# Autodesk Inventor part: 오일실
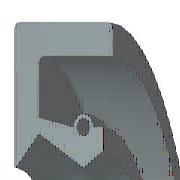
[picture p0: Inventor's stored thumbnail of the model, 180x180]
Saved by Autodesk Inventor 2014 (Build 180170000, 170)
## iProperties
Created: 2009-02
Part Number: 오일실
Material: 고무
Description: 오일-실
Document SubType Name: Modeling
Standard: KS B 2804
Designer: SeoGD™
Standards Organization: KS
Language: ko-KR
Size Designation: D - 10 20 7
Categories: <MemberInstance><Categories><Category DisplayName="샤프트 부품" InternalName="7f7aeb1f-a693-4053-b835-cee3144e0d98" Mnemonic="SHFT"><Category DisplayName="실링" Intern
Density: 0.93 g/cm^3
Mass: 1.11329 g
Surface Area: 16.3871 cm^2
Volume: 1.19708 cm^3
Appearance: 고무 - 검은색 - 버전 1.1
IsCustomPart: 0
Author: SeoGD™
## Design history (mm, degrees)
revolve "본체" stored, may be unused: angle "d17" = 90 deg
revolve "스프링1" stored, may be unused: angle "d18" = 90 deg
body "Solid1"
sketch "스케치1"
  geometry: L1 (0, 10)-(7, 10); L2 (7, 8.25)-(1.75, 8.25); L3 (1.75, 6.75)-(4.9, 5); L4 (4.9, 5)-(0, 5); L5 (0, 0)-(9.586, 0) reference; L6 (4.9, 5)-(6.3, 5.875); L7 (0, 18)-(0, -3) reference; L8 (-1.941, 0)-(11.507, 0) reference; L9 (4.2, 7.1)-(1.75, 7.59); L10 (1.75, 7.59)-(1.75, 8.25); L11 (0, 10)-(0, 5.088); L12 (4.9, 5)-(0, 5); L13 (1.75, 6.75)-(0.152, 5.028); L14 (7, 10)-(7, 8.25); L15 (5.6, 7.1)-(6.3, 7.1); L16 (6.3, 7.1)-(6.3, 5.875); C1 r 0.455 at (4.9, 7.1); A1 r 0.7 centre (4.9, 7.1) between (5.6, 7.1) and (4.2, 7.1); A2 r 0.088 centre (0.088, 5.088) between (0, 5.088) and (0.152, 5.028); 1 further point
  constraints: 28 end point, 5 horizontal alignment, 5 point on line, 4 point on circle, 4 vertical alignment, 3 centre point, 3 tangent, 2 collinear, 2 horizontal, 2 perpendicular, 1 coincident, 1 parallel
  dimensions: "d0" = 20 diameter of L1 L5 (= SD2); "d1" = 1.75 distance of L1.end L2.start (= SD); "d2" = 0.91 diameter of C1 (= SPDI); "d3" = 1.4 diameter of A1 (= SPDA); "d4" = 10 diameter of L3.end L5 (= NND); "d5" = 13.5 diameter of L3.start L5 (= TKDM); "d7" = 15.18 diameter of L9.end L5 (= TKDM + 0.24 x SWDT); "d8" = 1.75 distance between parallel lines of L11 L10 (= SD); "d9" = 4.9 distance from line of L11 C1.centre (= SPDST); "d10" = 14.2 diameter of C1.centre L5 (= HLDM); "d11" = 0.0875 radius of A2 (= 0.25 x LAB); "d12" = 6.3 distance between parallel lines of L11 L16 (= SDI); "d13" = 11.75 diameter of L6.end L5 (= ABDM); "d14" = 7 distance from line of L11 L1.end (= SWDT)
fillet "모깎기1" dims "d6" = 0.3 (= RR)
other parameters: "SD2" = 20 [user parameter; used in 1 equation term], "SWDT" = 7 [user parameter; used in 2 equation terms], "RR" = 0.3 [user parameter; used in 1 equation term], "SD" = 1.75 [user parameter; used in 2 equation terms], "NND" = 10 [user parameter; used in 1 equation term], "SPDA" = 1.4 [user parameter; used in 1 equation term], "SPDI" = 0.91 [user parameter; used in 1 equation term], "TKDM" = 13.5 [user parameter; used in 2 equation terms], "HLDM" = 14.2 [user parameter; used in 1 equation term], "ABDM" = 11.75 [user parameter; used in 1 equation term], "SDI" = 6.3 [user parameter; used in 1 equation term], "SPDST" = 4.9 [user parameter; used in 1 equation term], "LAB" = 0.35 [user parameter; used in 1 equation term], "d15" = 0, "d16" = 0, "d19" = 0
